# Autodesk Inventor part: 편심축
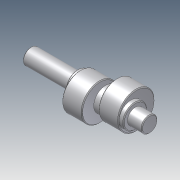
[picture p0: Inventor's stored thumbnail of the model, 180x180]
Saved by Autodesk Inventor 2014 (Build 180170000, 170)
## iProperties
Company: 한국ATC센터
Created: 2014-01
Part Number: 편심축
Document SubType Name: Modeling
Designer: KYOUNG IL JANG
Density: 1 g/cm^3
Material: 일반
Mass: 122.723 g
Surface Area: 190.471 cm^2
Volume: 122.723 cm^3
Vendor: CBT Solutions
Appearance: 기본값
Author: KYOUNG IL JANG
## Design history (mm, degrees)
sketch "스케치1"
  geometry: L1 (70, -32)-(70, 32) reference; L2 (87, -18.2)-(87, 18.2) reference; L3 (-62, 0)-(88, 0); L4 (88, 0)-(88, 10); L5 (88, 10)-(70, 10); L6 (70, 10)-(70, 15); L7 (70, 15)-(-3, 15); L8 (-3, 15)-(-3, 10); L9 (-3, 10)-(-62, 10); L10 (-62, 10)-(-62, 0); L11 (66, 70)-(38, 70) reference; L12 (34, 70)-(6, 70) reference; L13 (52, 70)-(52, 15); L14 (20, 70)-(20, 15); 1 further point
  constraints: 20 end point, 6 perpendicular, 5 point on line, 3 parallel, 2 midpoint, 1 collinear
  dimensions: "d0" = 1 distance from line of L3.end L2; "d1" = 20 diameter of L5 L3; "d2" = 30 diameter of L7 L3; "d3" = 73 distance of L6.end L7.end; "d18" = 150 distance of L3.start L3.end
  node "참조1"
  node "참조2"
  node "참조3"
  node "참조4"
revolve "회전1" stored, may be unused: angle "d4" = 90 deg
node "작업 평면1"
sketch "스케치2"
  geometry: C1 r 15 at (70, 0) reference; C2 r 23 at (63, 0); 1 further point
  constraints: 1 centre point, 1 horizontal alignment
  dimensions: "d6" = 7 distance of C2.centre C1.centre; "d7" = 46 diameter of C2
extrude "돌출1" join sketch "스케치2" stored distance "d8" = 25; taper "d9" = 0 deg
node "작업 평면2"
sketch "스케치3"
  geometry: C1 r 15 at (70, 0) reference; C2 r 23 at (77, 0); 1 further point
  constraints: 1 centre point, 1 horizontal alignment
  dimensions: "d11" = 46 diameter of C2 (= d7); "d12" = 7 distance of C2.centre point (70, 0) (= d6)
extrude "돌출2" join sketch "스케치3" stored distance "d13" = 25; taper "d14" = 0 deg
chamfer "모따기1" distance "d15" = 1; stored, may be unused: second distance "d16" = 2, angle "d17" = 45 deg
node "작업 평면3"
sketch "스케치4"
  geometry: L1 (29.5, 9)-(29.5, -9) reference; L2 (29.5, 3)-(12.5, 3); L3 (12.5, -3)-(29.5, -3); A1 r 3 centre (12.5, 0) between (12.5, 3) and (12.5, -3); 2 further points
  constraints: 4 end point, 2 perpendicular, 2 point on circle, 2 point on line, 2 tangent, 1 centre point, 1 horizontal alignment, 1 midpoint
  dimensions: "d19" = 20 dimension on A1 L1; "d20" = 6 distance between parallel lines of L3 L2
extrude "돌출3" cut sketch "스케치4" distance "d21" = 3.5; taper "d22" = 0 deg
chamfer "모따기2" distance "d23" = 1; stored, may be unused: second distance "d24" = 2, angle "d25" = 45 deg
sketch "스케치5"
  geometry: L1 (8.5, 16)-(8.5, -30) reference; L2 (31.5, 16)-(8.5, 16) reference; L3 (8.5, -7)-(100.304, -7); L4 (63.5, 30)-(40.5, 30) reference; L5 (40.5, 30)-(40.5, -16) reference; L6 (40.5, 7)-(102.22, 7); A1 r 30 centre (20, 45.394) between (14, 16) and (26, 16); A2 r 30 centre (52, 59.394) between (46, 30) and (58, 30); 3 further points
  constraints: 4 end point, 4 midpoint, 4 point on circle, 4 point on line, 2 centre point, 2 parallel, 2 vertical alignment, 1 perpendicular
  dimensions: "d27" = 30 radius of A1; "d28" = 6 distance of A1.start point (20, 16); "d30" = 6 distance of A2.start point (52, 30) (= d28); "d31" = 30 radius of A2 (= d27)
node "솔리드1"
other parameters: "d5" = 0, "d10" = 0
